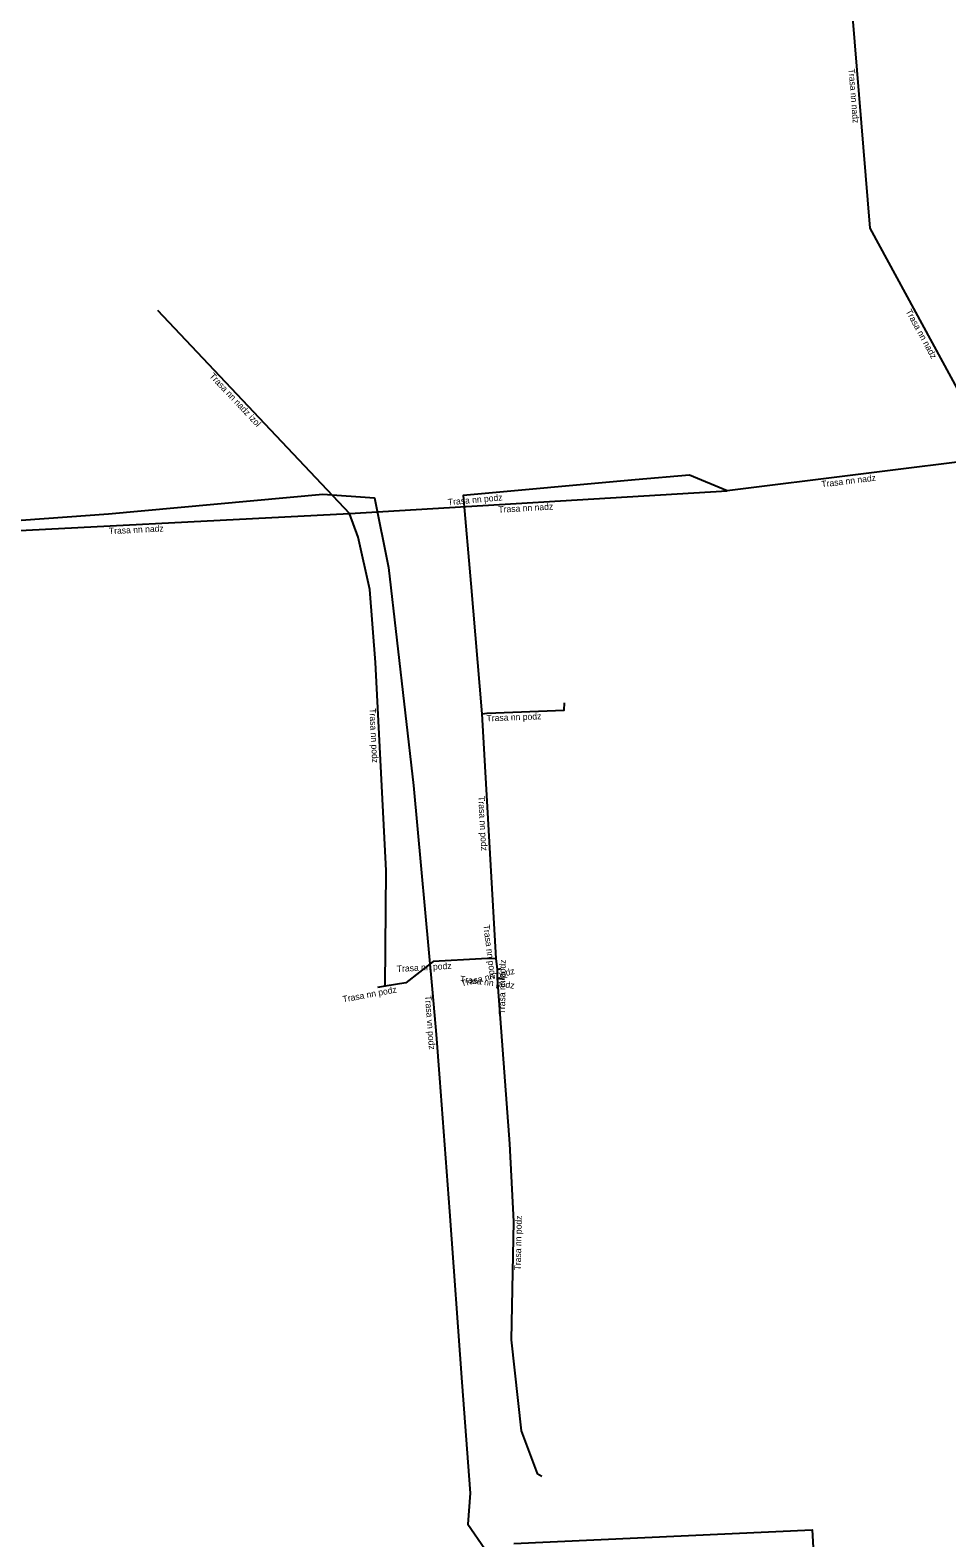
# Model space of a CAD drawing. Extents: x -682739 to -681564, y -1060091 to -1059590.
# Drawn here: x -682252.8 to -682181.4, y -1059876.8 to -1059759.2 of the extents above; entities that cross this region are included whole.
import ezdxf

# ---------------------------------------------------------------- set-up
doc = ezdxf.new("R2010")
doc.units = 0
for name, color, linetype in [('Popiskový text - Ostatní atributy Trasy', 7, 'Continuous'), ('Spojnice NN', 7, 'Continuous'), ('Spojnice VN', 7, 'Continuous')]:
    doc.layers.add(name, color=color, linetype=linetype)

msp = doc.modelspace()

# ---------------------------------------------------------------- linework, layer by layer
at = {"layer": 'Spojnice NN'}
for points in [[(-682188.9, -1059756.02), (-682187.38, -1059774.68)], [(-682187.38, -1059774.68), (-682177.66, -1059792.56)], [(-682242.9, -1059781.06), (-682227.92, -1059796.92)], [(-682177.66, -1059792.56), (-682198.49, -1059795.15)], [(-682198.49, -1059795.15), (-682201.43, -1059793.93), (-682205.66, -1059794.29), (-682219.07, -1059795.53), (-682218.47, -1059802.37), (-682217.62, -1059812.54)], [(-682227.92, -1059796.92), (-682198.49, -1059795.15)], [(-682259.21, -1059798.53), (-682227.92, -1059796.92)], [(-682225.15, -1059833.77), (-682225.07, -1059824.75), (-682225.91, -1059808.55), (-682226.35, -1059802.85), (-682227.25, -1059798.78), (-682227.92, -1059796.92)], [(-682217.62, -1059812.54), (-682217.21, -1059812.48), (-682211.19, -1059812.25), (-682211.16, -1059811.68)], [(-682217.62, -1059812.54), (-682216.52, -1059831.62)], [(-682216.52, -1059831.62), (-682217.64, -1059831.63), (-682221.4, -1059831.85), (-682223.55, -1059833.52), (-682225.15, -1059833.77)], [(-682216.52, -1059831.62), (-682216.41, -1059832.47)], [(-682216.41, -1059832.47), (-682216.42, -1059833.15)], [(-682216.42, -1059833.15), (-682215.45, -1059846.05), (-682215.16, -1059852.12), (-682215.34, -1059861.33), (-682214.55, -1059868.44), (-682213.31, -1059871.75), (-682212.95, -1059871.97)], [(-682216.42, -1059833.15), (-682215.85, -1059833.22)], [(-682216.41, -1059832.47), (-682216.12, -1059832.4)], [(-682225.15, -1059833.77), (-682225.74, -1059833.88)]]:
    msp.add_lwpolyline(points, dxfattribs=at)
at = {"layer": 'Spojnice VN'}
for points in [[(-682419.71, -1059843.18), (-682409.04, -1059841.86), (-682401.8, -1059840.66), (-682391.43, -1059837.47), (-682378.96, -1059833.37), (-682366.87, -1059827.88), (-682350.77, -1059821.14), (-682334.98, -1059814.51), (-682322.31, -1059809.45), (-682316.78, -1059807.47), (-682307.06, -1059804.21), (-682298.09, -1059802), (-682285.23, -1059800.25), (-682273.9, -1059799.1), (-682259.98, -1059797.91), (-682246.72, -1059796.96), (-682230, -1059795.42), (-682225.98, -1059795.71), (-682224.89, -1059801.14), (-682222.94, -1059818.12), (-682221.47, -1059834.28)], [(-682221.47, -1059834.28), (-682221.17, -1059837.54), (-682220.92, -1059840.93)], [(-682220.92, -1059840.93), (-682220.13, -1059851.34), (-682219.17, -1059864.65), (-682218.53, -1059873.29), (-682218.7, -1059875.7), (-682217.37, -1059877.62)], [(-682215.11, -1059877.22), (-682191.87, -1059876.16), (-682191.09, -1059889.98)]]:
    msp.add_lwpolyline(points, dxfattribs=at)

# ---------------------------------------------------------------- texts
at = {"layer": 'Popiskový text - Ostatní atributy Trasy'}
for s, rotation, p in [('Trasa nn nadz', 274.6322, (-682189.04, -1059762.26)), ('Trasa nn nadz', 298.5311, (-682184.6, -1059781.16)), ('Trasa nn nadz izol', 313.356, (-682238.89, -1059786.24)), ('Trasa nn nadz', 7.1, (-682191.12, -1059794.89)), ('Trasa nn podz', 5.283, (-682220.24, -1059796.29)), ('Trasa nn nadz', 3.4418, (-682216.31, -1059796.87)), ('Trasa nn nadz', 2.9455, (-682246.67, -1059798.54)), ('Trasa nn podz', 272.9682, (-682226.38, -1059812.12)), ('Trasa nn podz', 2.158, (-682217.24, -1059813.13)), ('Trasa nn podz', 273.2996, (-682217.9, -1059818.97)), ('Trasa nn podz', 277.3738, (-682217.51, -1059829.01)), ('Trasa nn podz', 3.3486, (-682224.23, -1059832.67)), ('Trasa nn podz', 89.1575, (-682215.81, -1059835.97)), ('Trasa nn podz', 13.5704, (-682219.17, -1059833.81)), ('Trasa nn podz', 352.9987, (-682219.34, -1059833.45)), ('Trasa nn podz', 10.561, (-682228.42, -1059835.04)), ('Trasa vn podz', 274.3079, (-682222.05, -1059834.51)), ('Trasa nn podz', 88.8804, (-682214.58, -1059855.93))]:
    msp.add_text(s, height=0.5, rotation=rotation, dxfattribs=at).set_placement(p)

doc.saveas('drawing.dxf')
